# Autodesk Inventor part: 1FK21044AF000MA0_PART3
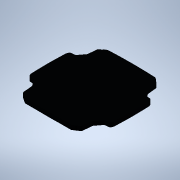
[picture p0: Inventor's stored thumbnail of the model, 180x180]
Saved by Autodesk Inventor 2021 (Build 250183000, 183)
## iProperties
Created: 2025-04
Part Number: 1FK21044AF000MA0_PART3
Material: Generic
Catalog Web Link: www.3dfindit.com
Description: -Servo synchronous motor
Document SubType Name: Modeling
Designer: psAdmin
Mass: 21.7019 g
Surface Area: 120.085 cm^2
Volume: 21.7019 cm^3
Density: 1 g/cm^3
Appearance: PSOLRGB-38-46-56
Category: PARTsolutions
Title: 1FK21044AF000MA0_PART3
Author: Cadenas PARTsolutions
Comments: Servo synchronous motor
Sending System: PARTsolutions
Preprocessor: ST-DEVELOPER v19.3
PSOL_IDENT_0: {$CADENAS_DATA/23d-libs/siemens_ag/_cat_/39/c4/1fk21044af000ma0.prj},213 {VTYP=3D},{NB=1FK21044AF000
PSOL_IDENT_1: MA0_PART3},{LINA=1FK21044AF000MA0_PART3},{NN=1FK21044AF000MA0_PART3},{NOPRJ=TRUE},{DATE=19.08.2025 1
PSOL_IDENT_2: 4:00:33},{GEOMDATE=30.07.2025 02:02:22},{VERSION=},{LINEID=10},{WBVAR=},{WBNUMERIC=}  {NB=1FK21044AF
PSOL_IDENT_3: 000MA0_PART3},{LINA=1FK21044AF000MA0_PART3},{KT=DUMMY},{PREVIEW=../../../_pool_/cb/72/p_d211_xx_0043
PSOL_IDENT_4: 4j.png},{DESCSHORT=SIMOTICS S-1FK2 HD, SINAMICS S210 3AC 400V-480V, 1.27 Nm, 3000 rpm},{DESCLONG=SIM
PSOL_IDENT_5: OTICS S-1FK2 HD servo motor M0=1.27 Nm; PN = 0.4 kW at nN=3000 rpm (380-480 V); PN = 0.2 kW at nN=15
PSOL_IDENT_6: 00 rpm (200-240 V); degree of protection IP64; cylindrical shaft D19x40mm; absolute encoder 22-bit +
PSOL_IDENT_7: 12-bit multiturn (encoder AM22DQC); with OCC interface; plug size M17, rotatable; SIMOTICS S-1FK2 s
PSOL_IDENT_8: ervomotorfor a wide range of uses in industrial environments. SIMOTICS S‑1FK2 servomotors are compac
PSOL_IDENT_9: t synchronous motors with a high dynamic performance that set themselves apart as a result of their
PSOL_IDENT_10: high power density, degree of protection and overload capability. The motors are available in two va
PSOL_IDENT_11: riants: as High Dynamic variant (highest dynamic performance as a result of the low intrinsic moment
PSOL_IDENT_12: of inertia for applications demanding a high dynamic performance with low moved masses) - and as Co
PSOL_IDENT_13: mpact variant (precise and stable closed-loop control for medium up to large moved masses as a resul
PSOL_IDENT_14: t of a medium intrinsic moment of inertia). SIMOTICSS‑1FK2 servomotors fully exploit their strengths
PSOL_IDENT_15: in a system with the SINAMICSS210 frequency converter and simple connection using the one cable con
PSOL_IDENT_16: nection (OCC). Advantages include the short control and positioning times, fast and precise correcti
PSOL_IDENT_17: on of disturbing quantities as well as stable control with a high dynamic performance. The servo mot
PSOL_IDENT_18: ors can be configured to address a wide range of requirements. For example with and without holding
PSOL_IDENT_19: brake, IP64 or IP65 degree of protection, singleturn or multiturn absolute encoders - to name just a
PSOL_IDENT_20: few. Further, the servomotors are available in different shaft heights extending from 20 to 100. A
PSOL_IDENT_21: shaft sealing ring is available to achieve an IP65 degree of protection and for subsequent mounting
PSOL_IDENT_22: at the motor or as spare part. SIMOTICS - the optimum motor for each and every motion control applic
PSOL_IDENT_23: ation.},{INTNO=804766906428},{SUPPLIERALTNO=1FK2104-4AF00-0MA0},{MANUID=1FK21044AF000MA0},{MANUNAME=
PSOL_IDENT_24: Siemens},{MANUTYPEDESC=Synchronous motor 1FK2-HD 1.27 NM},{AAU732=SIMOTICS},{AAO057=S-1FK2},{AAU734=
PSOL_IDENT_25: SIMOTICS S-1FK2 HD servo motor M0=1.27 Nm; PN = 0.4 kW at nN=3000 rpm (380-480 V); PN = 0.2 kW at nN=
PSOL_IDENT_26: 1500 rpm (200-240 V); degree of protection IP64; cylindrical shaft D19x40mm; absolute encoder 22-bit
PSOL_IDENT_27: + 12-bit multiturn (encoder AM22DQC); with OCC interface; plug size M17, rotatable;},{AAW338=Synchr
PSOL_IDENT_28: onous motor 1FK2-HD 1.27 NM},{AAO742=SIMOTICS},{AAO663=4042948693322},{NOCUPEROU=1},{PRICEQUANTITY=1
PSOL_IDENT_29: },{QUANTITYMIN=1},{QUANTITYINT=1},{CTN=85015100},{COO=DE},{AAO676=1FK2104-4AF00-0MA0},{AAO677=Siemen
PSOL_IDENT_30: s AG},{ORDERUNIT=C62},{CONTENTUNIT=C62}
NB: 1FK21044AF000MA0_PART3
NT: Servo synchronous motor
NBSYN: $MANUID._PART3
LINA: 1FK21044AF000MA0_PART3
CATALOG: SIEMENS
PREVIEW: ../../../_pool_/cb/72/p_d211_xx_00434j.png
DESCSHORT: SIMOTICS S-1FK2 HD, SINAMICS S210 3AC 400V-480V, 1.27 Nm, 3000 rpm
DESCLONG: SIMOTICS S-1FK2 HD servo motor M0=1.27 Nm; PN = 0.4 kW at nN=3000 rpm (380-480 V); PN = 0.2 kW at nN=1500 rpm (200-240 V); degree of protection IP64; cylindrica
INTNO: 804766906428
SUPPLIERALTNO: 1FK2104-4AF00-0MA0
MANUID: 1FK21044AF000MA0
MANUNAME: Siemens
MANUTYPEDESC: Synchronous motor 1FK2-HD 1.27 NM
AAU732: SIMOTICS
AAO057: S-1FK2
AAU734: SIMOTICS S-1FK2 HD servo motor M0=1.27 Nm; PN = 0.4 kW at nN=3000 rpm (380-480 V); PN = 0.2 kW at nN=1500 rpm (200-240 V); degree of protection IP64; cylindrica
AAW338: Synchronous motor 1FK2-HD 1.27 NM
AAO742: SIMOTICS
AAO663: 4042948693322.0
NOCUPEROU: 1
PRICEQUANTITY: 1
QUANTITYMIN: 1
QUANTITYINT: 1
CTN: 85015100
COO: DE
ARTICLENO: 1FK21044AF000MA0_PART3
BOMINFO: 1FK21044AF000MA0_PART3
CREATOR: CADENAS GmbH
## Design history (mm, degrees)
feature "2025_04_17_15_01_27_0944"
body "Solid1"
